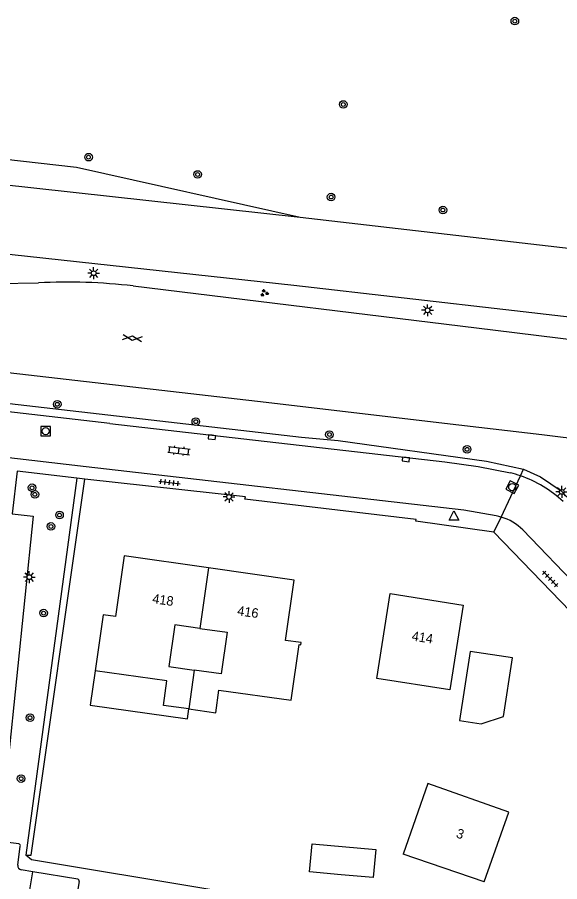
# Model space of a CAD drawing. Extents: x 132994 to 136000, y 393499 to 395512.
# Drawn here: x 133793.3 to 133850.3, y 394951.9 to 395042.7 of the extents above; entities that cross this region are included whole.
import ezdxf

# ---------------------------------------------------------------- set-up
doc = ezdxf.new("R2010")
doc.units = 0
for name, color, linetype in [('gg-afsc-hekwerk', 7, 'Continuous'), ('gg-anno-huisnummerreeks BGT', 7, 'Continuous'), ('gg-bbg-bijgebouw', 7, 'Continuous'), ('gg-bbg-gedigitaliseerde bebouwing', 7, 'Continuous'), ('gg-bbg-hoofdgebouw', 7, 'Continuous'), ('gg-bbg-luifel en loopbrug', 7, 'Continuous'), ('gg-bbg-tussenscheiding', 7, 'Continuous'), ('gg-knt-verharding', 7, 'Continuous'), ('gg-knt-verharding nz', 7, 'Continuous'), ('gt-grn-groengrens', 7, 'Continuous'), ('gt-grn-weggrens', 7, 'Continuous'), ('gt-symb-boom', 7, 'Continuous'), ('gt-symb-gesloten verharding', 7, 'Continuous'), ('gt-symb-groenvak', 7, 'Continuous'), ('gt-symb-klinker verharding', 7, 'Continuous'), ('gt-symb-kolk', 7, 'Continuous'), ('gt-symb-lichtmast', 7, 'Continuous'), ('gt-symb-rioolschacht', 7, 'Continuous'), ('gt-symb-tegel verharding', 7, 'Continuous'), ('gt-symb-waterafsluiter', 7, 'Continuous')]:
    doc.layers.add(name, color=color, linetype=linetype)

# ---------------------------------------------------------------- blocks, each defined once
blk = doc.blocks.new('gt0-TEG1')
at = {"layer": 'gt-symb-tegel verharding'}
for p, q in [((-1.125, 0), (1.125, 0)), ((-0.9, -0.25), (-0.9, 0.25)), ((-0.45, -0.25), (-0.45, 0.25)), ((0, -0.25), (0, 0.25)), ((0.45, -0.25), (0.45, 0.25)), ((0.9, -0.25), (0.9, 0.25))]:
    blk.add_line(p, q, dxfattribs=at)
blk = doc.blocks.new('gt0-LMAST')
at = {"layer": 'gt-symb-lichtmast'}
for p, q in [((-0.182, 0.173), (-0.447, 0.438)), ((-0.005, 0.246), (-0.005, 0.621)), ((0.172, 0.173), (0.437, 0.438)), ((-0.255, -0.004), (-0.63, -0.004)), ((-0.182, -0.181), (-0.447, -0.446)), ((-0.005, -0.254), (-0.005, -0.629)), ((0.437, -0.446), (0.172, -0.181)), ((0.245, -0.004), (0.62, -0.004))]:
    blk.add_line(p, q, dxfattribs=at)
blk.add_circle((-0.005, -0.004), 0.25, dxfattribs=at)
blk = doc.blocks.new('gt0-GRVAK')
at = {"layer": 'gt-symb-groenvak'}
for p, q in [((-0.11, 0.189), (-0.228, 0.24)), ((-0.182, 0.153), (0.088, 0.153)), ((-0.091, 0.211), (-0.156, 0.322)), ((-0.047, 0.214), (-0.047, 0.393)), ((-0.004, 0.211), (0.061, 0.322)), ((0.015, 0.189), (0.133, 0.24)), ((0.262, -0.052), (0.197, 0.059)), ((0.305, -0.049), (0.305, 0.13)), ((0.349, -0.052), (0.414, 0.059)), ((-0.245, -0.228), (-0.363, -0.177)), ((-0.318, -0.264), (-0.047, -0.264)), ((-0.226, -0.206), (-0.291, -0.095)), ((-0.183, -0.203), (-0.183, -0.024)), ((-0.139, -0.206), (-0.074, -0.095)), ((-0.12, -0.228), (-0.002, -0.177)), ((0.243, -0.074), (0.125, -0.023)), ((0.17, -0.11), (0.441, -0.11)), ((0.368, -0.074), (0.486, -0.023))]:
    blk.add_line(p, q, dxfattribs=at)
blk = doc.blocks.new('gt0-BOOM')
at = {"layer": 'gt-symb-boom'}
for radius in [0.4, 0.2]:
    blk.add_circle((0, 0), radius, dxfattribs=at)
blk = doc.blocks.new('gt0-KOLK')
at = {"layer": 'gt-symb-kolk'}
blk.add_lwpolyline([(0, 0), (0.375, 0), (0.375, 0.4), (-0.375, 0.4), (-0.375, 0), (0, 0)], dxfattribs=at)
blk = doc.blocks.new('gt0-WAFSL')
at = {"layer": 'gt-symb-waterafsluiter'}
for p, q in [((-0.5, -0.333), (0, 0.667)), ((0, 0.667), (0.5, -0.333)), ((0.5, -0.333), (-0.5, -0.333))]:
    blk.add_line(p, q, dxfattribs=at)
blk = doc.blocks.new('gt0-RS')
at = {"layer": 'gt-symb-rioolschacht'}
blk.add_lwpolyline([(-0.5, -0.5), (0.5, -0.5), (0.5, 0.5), (-0.5, 0.5)], close=True, dxfattribs=at)
blk.add_circle((0, 0), 0.375, dxfattribs=at)
blk = doc.blocks.new('gt0-GESVH1')
at = {"layer": 'gt-symb-gesloten verharding'}
for p, q in [((-0.992, -0.261), (0.008, 0.239)), ((0.008, -0.261), (-0.992, 0.239)), ((0.008, 0.239), (1.008, -0.261)), ((1.008, 0.239), (0.008, -0.261))]:
    blk.add_line(p, q, dxfattribs=at)
blk = doc.blocks.new('gt0-KL1')
at = {"layer": 'gt-symb-klinker verharding'}
for p, q in [((-1.15, 0.3), (1.15, 0.3)), ((-1, -0.3), (-1, 0.3)), ((-0.5, 0.3), (-0.5, 0.45)), ((0, -0.3), (0, 0.3)), ((0.5, 0.3), (0.5, 0.45)), ((1, -0.3), (1, 0.3)), ((-1.15, -0.3), (1.15, -0.3)), ((-0.5, -0.45), (-0.5, -0.3)), ((0.5, -0.45), (0.5, -0.3))]:
    blk.add_line(p, q, dxfattribs=at)

msp = doc.modelspace()

# ---------------------------------------------------------------- linework, layer by layer
at = {"layer": 'gg-afsc-hekwerk'}
for p, q in [((133799.515, 394994.268), (133794.173, 394954.655)), ((133794.173, 394954.655), (133794.735, 394954.674))]:
    msp.add_line(p, q, dxfattribs=at)
at = {"layer": 'gg-bbg-bijgebouw'}
for points in [[(133839.722, 394968.798), (133841.996, 394968.464), (133844.362, 394969.238), (133845.307, 394975.385), (133840.84, 394976.071), (133839.722, 394968.798)], [(133827.309, 394952.603), (133823.954, 394952.902), (133824.236, 394955.858), (133830.945, 394955.26), (133830.663, 394952.304), (133827.309, 394952.603)]]:
    msp.add_lwpolyline(points, dxfattribs=at)
at = {"layer": 'gg-bbg-gedigitaliseerde bebouwing'}
for points in [[(133812.467, 394978.476), (133809.82, 394978.847), (133809.208, 394974.472), (133811.86, 394974.101)], [(133812.467, 394978.476), (133815.312, 394978.078), (133814.7, 394973.703), (133811.86, 394974.101)], [(133811.291, 394970.027), (133814.129, 394969.63), (133814.461, 394971.995), (133822.05, 394970.932), (133822.869, 394976.78)], [(133811.291, 394970.027), (133808.637, 394970.399), (133808.997, 394972.974), (133801.449, 394974.03)], [(133842.32, 394951.88), (133844.89, 394959.196), (133836.394, 394962.18), (133833.791, 394954.771)]]:
    msp.add_lwpolyline(points, dxfattribs=at)
at = {"layer": 'gg-bbg-hoofdgebouw'}
for p, q in [((133802.288, 394979.91), (133801.449, 394974.03)), ((133842.32, 394951.88), (133833.791, 394954.771))]:
    msp.add_line(p, q, dxfattribs=at)
for points in [[(133813.35, 394984.841), (133804.5, 394986.1), (133803.589, 394979.72), (133802.288, 394979.91)], [(133822.869, 394976.78), (133823.069, 394976.75), (133823.108, 394976.99), (133821.439, 394977.22), (133822.349, 394983.56), (133813.35, 394984.841)], [(133832.44, 394982.13), (133840.11, 394980.91), (133838.709, 394972.021), (133831.036, 394973.231), (133832.44, 394982.13)]]:
    msp.add_lwpolyline(points, dxfattribs=at)
at = {"layer": 'gg-bbg-luifel en loopbrug'}
msp.add_lwpolyline([(133801.449, 394974.03), (133800.936, 394970.432), (133811.141, 394968.975), (133811.291, 394970.027)], dxfattribs=at)
at = {"layer": 'gg-bbg-tussenscheiding'}
for p, q in [((133813.35, 394984.841), (133812.467, 394978.476)), ((133811.86, 394974.101), (133811.291, 394970.027))]:
    msp.add_line(p, q, dxfattribs=at)
at = {"layer": 'gg-knt-verharding'}
for p, q in [((133822.979, 395021.635), (133746.282, 395030.078)), ((133860.232, 395017.337), (133822.979, 395021.635)), ((133781.477, 395014.524), (133795.502, 395014.768)), ((133800.526, 394995.439), (133784.178, 394997.345)), ((133799.515, 394994.268), (133793.265, 394994.982)), ((133800.38, 394994.169), (133799.515, 394994.268)), ((133859.247, 394972.063), (133843.346, 394988.59)), ((133862.288, 394972.217), (133846.386, 394988.819)), ((133793.45, 394955.847), (133791.413, 394956.085)), ((133793.319, 394953.623), (133793.588, 394955.61)), ((133794.905, 394952.912), (133793.689, 394953.126)), ((133799.625, 394952.135), (133794.905, 394952.912))]:
    msp.add_line(p, q, dxfattribs=at)
for points in [[(133822.979, 395021.635), (133799.512, 395026.89), (133768.813, 395030.34), (133746.282, 395030.078)], [(133874.225, 395008.567), (133868.836, 395009.122), (133845.49, 395011.838), (133822.318, 395014.495), (133750.599, 395022.315), (133724.94, 395025.159), (133706.97, 395027.168), (133704.01, 395027.246), (133686.896, 395026.871)], [(133805.447, 395014.45), (133843.211, 395009.853), (133873.927, 395006.07)], [(133803.009, 395000), (133772.607, 395003.5), (133760.688, 395004.836), (133757.228, 395005.351), (133735.229, 395009.073), (133733.476, 395009.301)], [(133838.166, 395000), (133819.405, 395002.212), (133767.315, 395008.188)], [(133803.009, 395000), (133838.189, 394995.98), (133841.67, 394995.471), (133845.097, 394994.808)], [(133863.026, 394996.992), (133848.377, 394998.796), (133838.166, 395000)], [(133843.588, 394990.299), (133840.17, 394990.885), (133800.526, 394995.439)], [(133793.265, 394994.982), (133792.755, 394990.502), (133794.936, 394990.265), (133791.413, 394956.085)], [(133843.346, 394988.59), (133835.124, 394989.731), (133835.184, 394989.927), (133817.179, 394992.038), (133817.262, 394992.289), (133800.38, 394994.169)], [(133799.789, 394951.91), (133796.104, 394929.998), (133791.639, 394930.748)]]:
    msp.add_lwpolyline(points, dxfattribs=at)
for centre, radius, start, end in [((133798.558, 394954.679), 60.167, 83.42551, 92.91158), ((133842.096, 394982.871), 12.308, 70.87481, 75.88976), ((133842.053, 394982.69), 12.494, 46.77674, 70.9578), ((133842.603, 394985.021), 5.369, 73.8828, 79.43428), ((133842.612, 394985.07), 5.32, 44.80942, 73.82349), ((133793.42, 394955.671), 0.179, 340.08223, 80.34042), ((133793.778, 394953.579), 0.461, 174.48086, 258.85206), ((133799.607, 394951.95), 0.186, 347.58571, 84.59008)]:
    msp.add_arc(centre, radius, start, end, dxfattribs=at)
at = {"layer": 'gg-knt-verharding nz'}
msp.add_line((133791.127, 394930.388), (133794.905, 394952.912), dxfattribs=at)
at = {"layer": 'gt-grn-groengrens'}
msp.add_line((133794.735, 394954.674), (133800.38, 394994.169), dxfattribs=at)
for points in [[(133568.55, 395027.016), (133598.605, 395024.265), (133629.508, 395021.349), (133654.602, 395018.736), (133699.62, 395013.815), (133719.54, 395011.607), (133729.257, 395010.661), (133736.756, 395009.518), (133740.544, 395009.001), (133753.397, 395006.823), (133760.835, 395005.738), (133823.139, 394998.553), (133826.998, 394998.206), (133842.575, 394996.032), (133846.453, 394995.188)], [(133846.453, 394995.188), (133848.227, 394994.385), (133850.419, 394992.944), (133855.435, 394987.641)], [(133813.504, 394951.058), (133794.773, 394954.191), (133794.173, 394954.655)]]:
    msp.add_lwpolyline(points, dxfattribs=at)
at = {"layer": 'gt-grn-weggrens'}
for p, q in [((133844.094, 394990.179), (133846.129, 394994.5)), ((133846.129, 394994.5), (133846.453, 394995.188)), ((133843.346, 394988.59), (133844.094, 394990.179))]:
    msp.add_line(p, q, dxfattribs=at)

# ---------------------------------------------------------------- block references
at = {"layer": 'gt-symb-boom'}
for p in [(133845.538, 395042.263), (133827.518, 395033.506), (133800.762, 395027.973), (133812.22, 395026.154), (133826.243, 395023.781), (133837.979, 395022.417), (133797.479, 395002.019), (133812.03, 395000.194), (133826.063, 394998.839), (133840.522, 394997.286), (133794.829, 394993.25), (133795.126, 394992.558), (133797.713, 394990.389), (133796.816, 394989.189), (133796.043, 394980.089), (133794.62, 394969.105), (133793.678, 394962.709)]:
    msp.add_blockref('gt0-BOOM', p, dxfattribs=at)
at = {"layer": 'gt-symb-gesloten verharding', "rotation": -6.485660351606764}
msp.add_blockref('gt0-GESVH1', (133805.352, 395008.972), dxfattribs=at)
at = {"layer": 'gt-symb-groenvak'}
msp.add_blockref('gt0-GRVAK', (133819.221, 395013.706), dxfattribs=at)
at = {"layer": 'gt-symb-klinker verharding', "rotation": -6.606034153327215}
msp.add_blockref('gt0-KL1', (133810.258, 394997.144), dxfattribs=at)
at = {"layer": 'gt-symb-kolk'}
for p, rotation in [((133813.744, 394998.759), 173.3939658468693), ((133834.11, 394996.431), 173.45090842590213)]:
    msp.add_blockref('gt0-KOLK', p, dxfattribs=dict(at, rotation=rotation))
at = {"layer": 'gt-symb-lichtmast'}
for p in [(133801.305, 395015.785), (133836.378, 395011.895), (133850.469, 394992.821), (133815.522, 394992.288), (133794.547, 394983.865)]:
    msp.add_blockref('gt0-LMAST', p, dxfattribs=at)
at = {"layer": 'gt-symb-rioolschacht'}
msp.add_blockref('gt0-RS', (133796.259, 394999.201), dxfattribs=at)
at = {"layer": 'gt-symb-rioolschacht', "rotation": -118.02531606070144}
msp.add_blockref('gt0-RS', (133845.265, 394993.318), dxfattribs=at)
at = {"layer": 'gt-symb-tegel verharding'}
for p, rotation in [((133809.258, 394993.807), -6.606034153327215), ((133849.249, 394983.683), 134.10862414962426)]:
    msp.add_blockref('gt0-TEG1', p, dxfattribs=dict(at, rotation=rotation))
at = {"layer": 'gt-symb-waterafsluiter'}
msp.add_blockref('gt0-WAFSL', (133839.145, 394990.173), dxfattribs=at)

# ---------------------------------------------------------------- texts
at = {"layer": 'gg-anno-huisnummerreeks BGT'}
for s, rotation, p in [('418', 351.9, (133807.411, 394981.14)), ('416', 351.9, (133816.335, 394979.87)), ('414', 351, (133834.655, 394977.22)), ('3', 341, (133839.292, 394956.558))]:
    msp.add_text(s, height=1, rotation=rotation, dxfattribs=at).set_placement(p)

doc.saveas('drawing.dxf')
